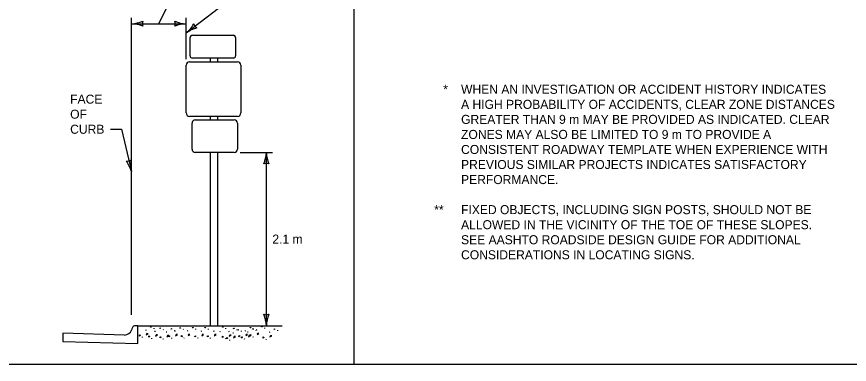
# Model space of a CAD drawing. Extents: x 49991.4 to 50021, y 49987.6 to 50011.4.
# Drawn here: x 50005.83 to 50011.36, y 49987.8 to 49990.11 of the extents above; entities that cross this region are included whole.
import ezdxf

# ---------------------------------------------------------------- set-up
doc = ezdxf.new("R2010")
doc.units = 0
for name, color, linetype in [('Level 1', 7, 'Continuous'), ('Level 2', 7, 'Continuous'), ('Level 3', 7, 'Continuous')]:
    doc.layers.add(name, color=color, linetype=linetype)

msp = doc.modelspace()

# ---------------------------------------------------------------- linework, layer by layer
at = {"layer": 'Level 1'}
for p, q in [((50006.9943, 49989.9861), (50007.2664, 49989.9861)), ((50006.9793, 49989.8499), (50006.9793, 49989.9711)), ((50007.2814, 49989.9711), (50007.2814, 49989.8499)), ((50007.2664, 49989.8349), (50006.9943, 49989.8349)), ((50007.1148, 49989.8098), (50007.1148, 49989.8349)), ((50007.1634, 49989.8098), (50007.1634, 49989.8349)), ((50006.9534, 49989.4698), (50006.9534, 49989.7873)), ((50006.9759, 49989.8098), (50007.2935, 49989.8098)), ((50007.316, 49989.7873), (50007.316, 49989.4698)), ((50007.2935, 49989.4473), (50006.9759, 49989.4473)), ((50007.1148, 49989.4234), (50007.1148, 49989.4473)), ((50007.1634, 49989.4234), (50007.1634, 49989.4473)), ((50006.9921, 49989.229), (50006.9921, 49989.4019)), ((50007.0136, 49989.4234), (50007.2728, 49989.4234)), ((50007.2943, 49989.4019), (50007.2943, 49989.229)), ((50007.2728, 49989.2075), (50007.0136, 49989.2075)), ((50007.1148, 49988.0554), (50007.1148, 49989.2075)), ((50007.1634, 49988.0554), (50007.1634, 49989.2075)), ((50006.6326, 49988.0554), (50006.6156, 49988.0554)), ((50006.6326, 49988.0554), (50007.5908, 49988.0554)), ((50006.6326, 49987.9369), (50006.6326, 49988.0554)), ((50006.7165, 49988.0456), (50006.7186, 49988.0503)), ((50006.7186, 49988.0503), (50006.721, 49988.0467)), ((50007.1939, 49988.0456), (50007.1959, 49988.0503)), ((50007.1959, 49988.0503), (50007.1984, 49988.0467)), ((50007.4531, 49988.0472), (50007.4551, 49988.0519)), ((50007.4575, 49988.0483), (50007.4531, 49988.0472)), ((50007.4551, 49988.0519), (50007.4575, 49988.0483)), ((50006.5443, 49987.9937), (50006.1327, 49988.006)), ((50006.1327, 49988.006), (50006.1327, 49987.9518)), ((50006.6429, 49987.9871), (50006.6434, 49987.9954)), ((50006.6492, 49987.9921), (50006.6429, 49987.9871)), ((50006.6434, 49987.9954), (50006.6492, 49987.9921)), ((50006.6866, 49988.0261), (50006.682, 49988.0245)), ((50006.6912, 49988.003), (50006.6879, 49987.9951)), ((50006.6879, 49987.9951), (50006.7, 49988.0028)), ((50006.7, 49988.0028), (50006.6912, 49988.003)), ((50006.721, 49988.0467), (50006.7165, 49988.0456)), ((50006.7394, 49988.036), (50006.7399, 49988.0396)), ((50006.7482, 49988.0181), (50006.7436, 49988.0165)), ((50006.7528, 49987.995), (50006.7495, 49987.9871)), ((50006.7495, 49987.9871), (50006.7616, 49987.9948)), ((50006.7616, 49987.9948), (50006.7528, 49987.995)), ((50006.7781, 49988.0376), (50006.7802, 49988.0423)), ((50006.7826, 49988.0387), (50006.7781, 49988.0376)), ((50006.7802, 49988.0423), (50006.7826, 49988.0387)), ((50006.8011, 49988.028), (50006.8015, 49988.0316)), ((50006.8241, 49988.0133), (50006.8195, 49988.0117)), ((50006.8541, 49988.0328), (50006.8561, 49988.0376)), ((50006.8585, 49988.0339), (50006.8541, 49988.0328)), ((50006.8561, 49988.0376), (50006.8585, 49988.0339)), ((50006.881, 49988.0197), (50006.8764, 49988.0182)), ((50006.877, 49988.0233), (50006.8775, 49988.0269)), ((50006.8856, 49987.9967), (50006.8823, 49987.9888)), ((50006.8823, 49987.9888), (50006.8944, 49987.9965)), ((50006.8944, 49987.9965), (50006.8856, 49987.9967)), ((50006.9109, 49988.0393), (50006.913, 49988.044)), ((50006.9154, 49988.0404), (50006.9109, 49988.0393)), ((50006.913, 49988.044), (50006.9154, 49988.0404)), ((50006.9339, 49988.0297), (50006.9343, 49988.0333)), ((50006.9648, 49988.0213), (50006.9602, 49988.0197)), ((50006.9694, 49987.9983), (50006.9661, 49987.9904)), ((50006.9661, 49987.9904), (50006.9782, 49987.998)), ((50006.9782, 49987.998), (50006.9694, 49987.9983)), ((50006.9947, 49988.0409), (50006.9968, 49988.0456)), ((50006.9992, 49988.0419), (50006.9947, 49988.0409)), ((50006.9968, 49988.0456), (50006.9992, 49988.0419)), ((50007.0177, 49988.0313), (50007.0181, 49988.0349)), ((50007.0549, 49988.0197), (50007.0503, 49988.0182)), ((50007.0595, 49987.9967), (50007.0562, 49987.9888)), ((50007.0562, 49987.9888), (50007.0684, 49987.9965)), ((50007.0684, 49987.9965), (50007.0595, 49987.9967)), ((50007.0777, 49988.0409), (50007.0798, 49988.0456)), ((50007.0822, 49988.0419), (50007.0777, 49988.0409)), ((50007.0798, 49988.0456), (50007.0822, 49988.0419)), ((50007.1007, 49988.0313), (50007.1011, 49988.0349)), ((50007.1379, 49988.0197), (50007.1333, 49988.0182)), ((50007.1425, 49987.9967), (50007.1392, 49987.9888)), ((50007.1392, 49987.9888), (50007.1514, 49987.9965)), ((50007.1514, 49987.9965), (50007.1425, 49987.9967)), ((50007.1797, 49988.0151), (50007.1801, 49988.0187)), ((50007.1984, 49988.0467), (50007.1939, 49988.0456)), ((50007.2168, 49988.036), (50007.2173, 49988.0396)), ((50007.2383, 49988.0165), (50007.2337, 49988.0149)), ((50007.2429, 49987.9934), (50007.2396, 49987.9855)), ((50007.2396, 49987.9855), (50007.2517, 49987.9932)), ((50007.2517, 49987.9932), (50007.2429, 49987.9934)), ((50007.2667, 49988.007), (50007.262, 49988.0054)), ((50007.2682, 49988.036), (50007.2703, 49988.0407)), ((50007.2727, 49988.0371), (50007.2682, 49988.036)), ((50007.2703, 49988.0407), (50007.2727, 49988.0371)), ((50007.2912, 49988.0264), (50007.2916, 49988.0301)), ((50007.2966, 49988.0265), (50007.2987, 49988.0313)), ((50007.3011, 49988.0276), (50007.2966, 49988.0265)), ((50007.2987, 49988.0313), (50007.3011, 49988.0276)), ((50007.3195, 49988.017), (50007.32, 49988.0206)), ((50007.3473, 49988.0213), (50007.3427, 49988.0197)), ((50007.3519, 49987.9983), (50007.3486, 49987.9904)), ((50007.3486, 49987.9904), (50007.3608, 49987.998)), ((50007.3608, 49987.998), (50007.3519, 49987.9983)), ((50007.3646, 49988.0133), (50007.36, 49988.0117)), ((50007.3773, 49988.0409), (50007.3793, 49988.0456)), ((50007.3817, 49988.0419), (50007.3773, 49988.0409)), ((50007.3793, 49988.0456), (50007.3817, 49988.0419)), ((50007.3794, 49987.9887), (50007.3799, 49987.9969)), ((50007.3857, 49987.9937), (50007.3794, 49987.9887)), ((50007.3799, 49987.9969), (50007.3857, 49987.9937)), ((50007.3946, 49988.0328), (50007.3967, 49988.0376)), ((50007.3991, 49988.0339), (50007.3946, 49988.0328)), ((50007.3967, 49988.0376), (50007.3991, 49988.0339)), ((50007.4002, 49988.0313), (50007.4007, 49988.0349)), ((50007.4175, 49988.0233), (50007.418, 49988.0269)), ((50007.4231, 49988.0276), (50007.4185, 49988.0261)), ((50007.4277, 49988.0046), (50007.4244, 49987.9967)), ((50007.4244, 49987.9967), (50007.4366, 49988.0043)), ((50007.4366, 49988.0043), (50007.4277, 49988.0046)), ((50007.476, 49988.0376), (50007.4765, 49988.0412)), ((50007.5085, 49988.0117), (50007.5039, 49988.0102)), ((50007.5384, 49988.0313), (50007.5405, 49988.036)), ((50007.5429, 49988.0324), (50007.5384, 49988.0313)), ((50007.5405, 49988.036), (50007.5429, 49988.0324)), ((50007.5614, 49988.0217), (50007.5618, 49988.0253)), ((50006.1327, 49987.9518), (50006.6326, 49987.9369)), ((50006.6617, 49987.9809), (50006.6601, 49987.9767)), ((50006.7045, 49987.9791), (50006.705, 49987.9874)), ((50006.7108, 49987.9841), (50006.7045, 49987.9791)), ((50006.705, 49987.9874), (50006.7108, 49987.9841)), ((50006.7233, 49987.9729), (50006.7217, 49987.9687)), ((50006.7804, 49987.9744), (50006.7809, 49987.9826)), ((50006.7867, 49987.9794), (50006.7804, 49987.9744)), ((50006.7809, 49987.9826), (50006.7867, 49987.9794)), ((50006.7992, 49987.9682), (50006.7977, 49987.964)), ((50006.8287, 49987.9903), (50006.8254, 49987.9824)), ((50006.8254, 49987.9824), (50006.8376, 49987.99)), ((50006.8376, 49987.99), (50006.8287, 49987.9903)), ((50006.8373, 49987.9808), (50006.8378, 49987.9891)), ((50006.8436, 49987.9858), (50006.8373, 49987.9808)), ((50006.8378, 49987.9891), (50006.8436, 49987.9858)), ((50006.8561, 49987.9746), (50006.8545, 49987.9704)), ((50006.9211, 49987.9824), (50006.9216, 49987.9906)), ((50006.9274, 49987.9874), (50006.9211, 49987.9824)), ((50006.9216, 49987.9906), (50006.9274, 49987.9874)), ((50006.9399, 49987.9762), (50006.9383, 49987.972)), ((50007.0112, 49987.9808), (50007.0117, 49987.9891)), ((50007.0175, 49987.9858), (50007.0112, 49987.9808)), ((50007.0117, 49987.9891), (50007.0175, 49987.9858)), ((50007.03, 49987.9746), (50007.0285, 49987.9704)), ((50007.0942, 49987.9808), (50007.0947, 49987.9891)), ((50007.1005, 49987.9858), (50007.0942, 49987.9808)), ((50007.0947, 49987.9891), (50007.1005, 49987.9858)), ((50007.113, 49987.9746), (50007.1115, 49987.9704)), ((50007.1946, 49987.9775), (50007.1951, 49987.9858)), ((50007.2009, 49987.9825), (50007.1946, 49987.9775)), ((50007.1951, 49987.9858), (50007.2009, 49987.9825)), ((50007.2134, 49987.9714), (50007.2118, 49987.9671)), ((50007.223, 49987.9681), (50007.2235, 49987.9763)), ((50007.2293, 49987.9731), (50007.223, 49987.9681)), ((50007.2235, 49987.9763), (50007.2293, 49987.9731)), ((50007.2418, 49987.9619), (50007.2402, 49987.9577)), ((50007.2713, 49987.984), (50007.268, 49987.9761)), ((50007.268, 49987.9761), (50007.2801, 49987.9837)), ((50007.2801, 49987.9837), (50007.2713, 49987.984)), ((50007.3036, 49987.9824), (50007.3041, 49987.9906)), ((50007.3099, 49987.9874), (50007.3036, 49987.9824)), ((50007.3041, 49987.9906), (50007.3099, 49987.9874)), ((50007.3224, 49987.9762), (50007.3209, 49987.972)), ((50007.321, 49987.9744), (50007.3215, 49987.9826)), ((50007.3273, 49987.9794), (50007.321, 49987.9744)), ((50007.3215, 49987.9826), (50007.3273, 49987.9794)), ((50007.3398, 49987.9682), (50007.3382, 49987.964)), ((50007.3693, 49987.9903), (50007.366, 49987.9824)), ((50007.366, 49987.9824), (50007.3781, 49987.99)), ((50007.3781, 49987.99), (50007.3693, 49987.9903)), ((50007.3982, 49987.9825), (50007.3967, 49987.9783)), ((50007.4648, 49987.9728), (50007.4653, 49987.9811)), ((50007.4711, 49987.9778), (50007.4648, 49987.9728)), ((50007.4653, 49987.9811), (50007.4711, 49987.9778)), ((50007.4836, 49987.9666), (50007.482, 49987.9624)), ((50007.5131, 49987.9887), (50007.5098, 49987.9808)), ((50007.5098, 49987.9808), (50007.5219, 49987.9885)), ((50007.5219, 49987.9885), (50007.5131, 49987.9887))]:
    msp.add_line(p, q, dxfattribs=at)
msp.add_lwpolyline([(49999.3835, 49998.9992), (50016.7501, 49998.9992), (50016.7501, 49987.7988), (49999.3835, 49987.7988)], close=True, dxfattribs=at)
for centre, radius, start, end in [((50006.9943, 49989.9711), 0.015, 90, 180), ((50007.2664, 49989.9711), 0.015, 0, 90), ((50006.9943, 49989.8499), 0.015, 180, 270), ((50007.2664, 49989.8499), 0.015, 270, 0), ((50006.9759, 49989.7873), 0.0225, 90, 180), ((50007.2935, 49989.7873), 0.0225, 0, 90), ((50006.9759, 49989.4698), 0.0225, 180, 270), ((50007.2935, 49989.4698), 0.0225, 270, 0), ((50007.0136, 49989.4019), 0.0215, 90, 180), ((50007.2728, 49989.4019), 0.0215, 0, 90), ((50007.0136, 49989.229), 0.0215, 180, 270), ((50007.2728, 49989.229), 0.0215, 270, 0), ((50006.614, 49988.0361), 0.0194, 85.2999, 156.6889), ((50006.5439, 49988.0414), 0.0477, 270.4937, 342.4535), ((50006.6404, 49988.0161), 0.0521, 148.3066, 167.8949)]:
    msp.add_arc(centre, radius, start, end, dxfattribs=at)
at = {"layer": 'Level 3'}
for p, q in [((50008.0668, 49994.0732), (50008.0668, 49987.7988)), ((50006.7714, 49990.0628), (50006.8726, 49990.2661)), ((50006.9534, 49990.0018), (50007.2733, 49990.2484)), ((50006.5894, 49988.127), (50006.5894, 49990.1028)), ((50006.9534, 49989.8273), (50006.9534, 49990.1028)), ((50006.5894, 49990.0628), (50006.9534, 49990.0628)), ((50006.4506, 49989.3617), (50006.5226, 49989.3617)), ((50006.5226, 49989.3617), (50006.5894, 49989.0802)), ((50007.3128, 49989.2075), (50007.5256, 49989.2075)), ((50007.4856, 49988.0554), (50007.4856, 49989.2075))]:
    msp.add_line(p, q, dxfattribs=at)
for centre, radius, start, end in [((50006.5779, 49990.2955), 0.233, 272.8273, 292.0772), ((50006.5803, 49989.8407), 0.2223, 67.456, 87.6395), ((50006.7176, 49990.0628), 0.0548, 162.1388, 197.8612), ((50006.9626, 49990.2849), 0.2223, 247.456, 267.6395), ((50006.8252, 49990.0628), 0.0548, 342.1388, 17.8612), ((50006.9649, 49989.8301), 0.233, 92.8273, 112.0772), ((50006.8022, 49990.179), 0.233, 310.456, 329.7058), ((50007.0549, 49990.08), 0.0548, 199.7675, 235.4899), ((50007.0818, 49989.8202), 0.2223, 105.0847, 125.2682), ((50006.559, 49989.2048), 0.0548, 265.8498, 301.5721), ((50006.8074, 49989.124), 0.2223, 171.1669, 191.3505), ((50007.2635, 49989.2167), 0.2223, 337.456, 357.6395), ((50007.7183, 49989.219), 0.233, 182.8273, 202.0772), ((50006.3661, 49989.0139), 0.233, 16.5382, 35.7881), ((50007.4856, 49989.0793), 0.0548, 72.1388, 107.8612), ((50007.4856, 49988.1836), 0.0548, 252.1388, 287.8612), ((50007.2529, 49988.0439), 0.233, 2.8273, 22.0772), ((50007.7077, 49988.0462), 0.2223, 157.456, 177.6395)]:
    msp.add_arc(centre, radius, start, end, dxfattribs=at)

# ---------------------------------------------------------------- texts
at = {"layer": 'Level 2'}
for s, p in [('*', (50008.6606, 49989.5972)), ('WHEN AN INVESTIGATION OR ACCIDENT HISTORY INDICATES', (50008.7791, 49989.5972)), ('FACE', (50006.1824, 49989.5317)), ('A HIGH PROBABILITY OF ACCIDENTS, CLEAR ZONE DISTANCES', (50008.7791, 49989.4972)), ('OF', (50006.1824, 49989.4317)), ('GREATER THAN 9 m MAY BE PROVIDED AS INDICATED. CLEAR', (50008.7791, 49989.3972)), ('CURB', (50006.1824, 49989.3317)), ('ZONES MAY ALSO BE LIMITED TO 9 m TO PROVIDE A', (50008.7791, 49989.2972)), ('CONSISTENT ROADWAY TEMPLATE WHEN EXPERIENCE WITH', (50008.7791, 49989.1972)), ('PREVIOUS SIMILAR PROJECTS INDICATES SATISFACTORY', (50008.7791, 49989.0972)), ('PERFORMANCE.', (50008.7791, 49988.9972)), ('**', (50008.6006, 49988.7972)), ('FIXED OBJECTS, INCLUDING SIGN POSTS, SHOULD NOT BE', (50008.7791, 49988.7972)), ('ALLOWED IN THE VICINITY OF THE TOE OF THESE SLOPES.', (50008.7791, 49988.6972)), ('2.1 m', (50007.5256, 49988.6014)), ('SEE AASHTO ROADSIDE DESIGN GUIDE FOR ADDITIONAL', (50008.7791, 49988.5972)), ('CONSIDERATIONS IN LOCATING SIGNS.', (50008.7791, 49988.4972))]:
    msp.add_text(s, height=0.06, dxfattribs=at).set_placement(p)

doc.saveas('drawing.dxf')
